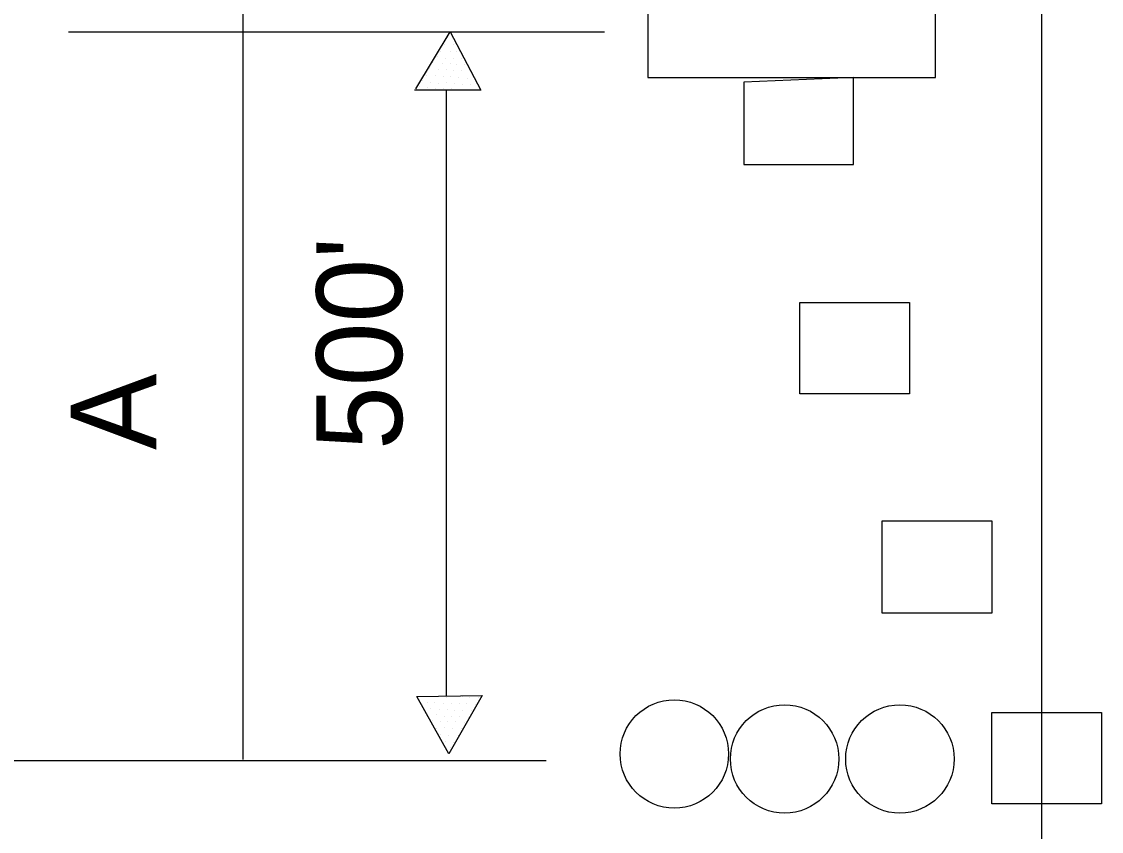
# Model space of a CAD drawing. Extents: x 610.92 to 617.75, y 610.91 to 620.34.
# Drawn here: x 615.094 to 615.85, y 618.032 to 618.599 of the extents above; entities that cross this region are included whole.
import ezdxf

# ---------------------------------------------------------------- set-up
doc = ezdxf.new("R2010")
doc.units = 0
for name, color, linetype in [('DETL-DIMS', 7, 'Continuous'), ('DETL-LINE', 7, 'Continuous'), ('DETL-NOTE', 7, 'Continuous'), ('USER-BORD', 7, 'Continuous')]:
    doc.layers.add(name, color=color, linetype=linetype)

# ---------------------------------------------------------------- blocks, each defined once
blk = doc.blocks.new('SIGN15')
at = {"layer": 'USER-BORD'}
for points in [[(-0.0013, 0.0018), (0.0011, 0.0019), (0.0011, 0.0037), (-0.0013, 0.0037)], [(-0.0031, 0.0018), (-0.0031, 0), (0.0032, 0), (0.0032, 0.0018)]]:
    blk.add_lwpolyline(points, close=True, dxfattribs=at)

msp = doc.modelspace()

# ---------------------------------------------------------------- linework, layer by layer
at = {"layer": 'DETL-DIMS'}
for p, q in [((615.24936, 618.082), (615.24936, 619.7948)), ((615.12696, 618.5916), (615.50216, 618.5916)), ((615.37016, 618.5516), (615.39416, 618.5916)), ((615.37016, 618.5516), (615.39416, 618.5916)), ((615.39416, 618.5916), (615.41576, 618.5508)), ((615.39416, 618.5916), (615.41576, 618.5508)), ((615.39016, 618.5828), (615.39016, 618.5828)), ((615.39016, 618.5828), (615.39016, 618.5828)), ((615.39256, 618.5876), (615.39256, 618.5876)), ((615.39256, 618.5876), (615.39256, 618.5876)), ((615.39656, 618.5828), (615.39656, 618.5828)), ((615.39656, 618.5828), (615.39656, 618.5828)), ((615.38776, 618.578), (615.38776, 618.578)), ((615.38776, 618.578), (615.38776, 618.578)), ((615.39416, 618.578), (615.39416, 618.578)), ((615.39416, 618.578), (615.39416, 618.578)), ((615.39896, 618.578), (615.39896, 618.578)), ((615.39896, 618.578), (615.39896, 618.578)), ((615.38216, 618.57), (615.38216, 618.57)), ((615.38216, 618.57), (615.38216, 618.57)), ((615.38536, 618.574), (615.38536, 618.574)), ((615.38536, 618.574), (615.38536, 618.574)), ((615.38856, 618.5692), (615.38856, 618.5692)), ((615.38856, 618.5692), (615.38856, 618.5692)), ((615.39096, 618.5732), (615.39096, 618.5732)), ((615.39096, 618.5732), (615.39096, 618.5732)), ((615.39416, 618.5692), (615.39416, 618.5692)), ((615.39416, 618.5692), (615.39416, 618.5692)), ((615.39656, 618.5732), (615.39656, 618.5732)), ((615.39656, 618.5732), (615.39656, 618.5732)), ((615.39896, 618.5684), (615.39896, 618.5684)), ((615.39896, 618.5684), (615.39896, 618.5684)), ((615.40216, 618.5732), (615.40216, 618.5732)), ((615.40216, 618.5732), (615.40216, 618.5732)), ((615.40456, 618.5684), (615.40456, 618.5684)), ((615.40456, 618.5684), (615.40456, 618.5684)), ((615.37736, 618.5612), (615.37736, 618.5612)), ((615.37736, 618.5612), (615.37736, 618.5612)), ((615.37976, 618.566), (615.37976, 618.566)), ((615.37976, 618.566), (615.37976, 618.566)), ((615.38376, 618.5612), (615.38376, 618.5612)), ((615.38376, 618.5612), (615.38376, 618.5612)), ((615.38616, 618.5652), (615.38616, 618.5652)), ((615.38616, 618.5652), (615.38616, 618.5652)), ((615.38936, 618.5604), (615.38936, 618.5604)), ((615.38936, 618.5604), (615.38936, 618.5604)), ((615.39176, 618.5652), (615.39176, 618.5652)), ((615.39176, 618.5652), (615.39176, 618.5652)), ((615.39416, 618.5604), (615.39416, 618.5604)), ((615.39416, 618.5604), (615.39416, 618.5604)), ((615.39656, 618.5644), (615.39656, 618.5644)), ((615.39656, 618.5644), (615.39656, 618.5644)), ((615.39976, 618.5596), (615.39976, 618.5596)), ((615.39976, 618.5596), (615.39976, 618.5596)), ((615.40216, 618.5644), (615.40216, 618.5644)), ((615.40216, 618.5644), (615.40216, 618.5644)), ((615.40856, 618.5636), (615.40856, 618.5636)), ((615.40856, 618.5636), (615.40856, 618.5636)), ((615.37256, 618.5532), (615.37256, 618.5532)), ((615.37256, 618.5532), (615.37256, 618.5532)), ((615.37496, 618.5572), (615.37496, 618.5572)), ((615.37496, 618.5572), (615.37496, 618.5572)), ((615.37816, 618.5524), (615.37816, 618.5524)), ((615.37816, 618.5524), (615.37816, 618.5524)), ((615.38056, 618.5564), (615.38056, 618.5564)), ((615.38056, 618.5564), (615.38056, 618.5564)), ((615.38616, 618.5556), (615.38616, 618.5556)), ((615.38616, 618.5556), (615.38616, 618.5556)), ((615.39176, 618.5564), (615.39176, 618.5564)), ((615.39176, 618.5564), (615.39176, 618.5564)), ((615.39736, 618.5556), (615.39736, 618.5556)), ((615.39736, 618.5556), (615.39736, 618.5556)), ((615.40296, 618.5548), (615.40296, 618.5548)), ((615.40296, 618.5548), (615.40296, 618.5548)), ((615.40616, 618.5588), (615.40616, 618.5588)), ((615.40616, 618.5588), (615.40616, 618.5588)), ((615.40856, 618.5548), (615.40856, 618.5548)), ((615.40856, 618.5548), (615.40856, 618.5548)), ((615.36936, 618.5508), (615.36936, 618.5508)), ((615.41576, 618.5508), (615.36936, 618.5508)), ((615.41576, 618.5508), (615.36936, 618.5508)), ((615.36936, 618.5508), (615.36936, 618.5508)), ((615.38376, 618.5516), (615.38376, 618.5516)), ((615.38376, 618.5516), (615.38376, 618.5516)), ((615.38936, 618.5516), (615.38936, 618.5516)), ((615.38936, 618.5516), (615.38936, 618.5516)), ((615.39176, 618.1268), (615.39176, 618.5508)), ((615.39176, 618.1268), (615.39176, 618.5508)), ((615.39496, 618.5516), (615.39496, 618.5516)), ((615.39496, 618.5516), (615.39496, 618.5516)), ((615.40056, 618.5508), (615.40056, 618.5508)), ((615.40056, 618.5508), (615.40056, 618.5508)), ((615.37096, 618.126), (615.41656, 618.1268)), ((615.37096, 618.126), (615.41656, 618.1268)), ((615.39336, 618.086), (615.37096, 618.126)), ((615.39336, 618.086), (615.37096, 618.126)), ((615.37816, 618.122), (615.37816, 618.122)), ((615.37816, 618.122), (615.37816, 618.122)), ((615.38296, 618.122), (615.38296, 618.122)), ((615.38296, 618.122), (615.38296, 618.122)), ((615.38536, 618.126), (615.38536, 618.126)), ((615.38536, 618.126), (615.38536, 618.126)), ((615.38936, 618.1212), (615.38936, 618.1212)), ((615.38936, 618.1212), (615.38936, 618.1212)), ((615.39176, 618.1252), (615.39176, 618.1252)), ((615.39176, 618.1252), (615.39176, 618.1252)), ((615.41656, 618.1268), (615.39336, 618.086)), ((615.41656, 618.1268), (615.39336, 618.086)), ((615.39496, 618.1212), (615.39496, 618.1212)), ((615.39496, 618.1212), (615.39496, 618.1212)), ((615.39736, 618.126), (615.39736, 618.126)), ((615.39736, 618.126), (615.39736, 618.126)), ((615.40056, 618.1212), (615.40056, 618.1212)), ((615.40056, 618.1212), (615.40056, 618.1212)), ((615.40296, 618.126), (615.40296, 618.126)), ((615.40296, 618.126), (615.40296, 618.126)), ((615.40536, 618.1212), (615.40536, 618.1212)), ((615.40536, 618.1212), (615.40536, 618.1212)), ((615.40776, 618.1252), (615.40776, 618.1252)), ((615.40776, 618.1252), (615.40776, 618.1252)), ((615.41416, 618.1252), (615.41416, 618.1252)), ((615.41416, 618.1252), (615.41416, 618.1252)), ((615.41656, 618.1268), (615.41656, 618.1268)), ((615.41656, 618.1268), (615.41656, 618.1268)), ((615.37816, 618.114), (615.37816, 618.114)), ((615.37816, 618.114), (615.37816, 618.114)), ((615.38056, 618.118), (615.38056, 618.118)), ((615.38056, 618.118), (615.38056, 618.118)), ((615.38456, 618.1132), (615.38456, 618.1132)), ((615.38456, 618.1132), (615.38456, 618.1132)), ((615.38696, 618.1172), (615.38696, 618.1172)), ((615.38696, 618.1172), (615.38696, 618.1172)), ((615.39256, 618.1172), (615.39256, 618.1172)), ((615.39256, 618.1172), (615.39256, 618.1172)), ((615.39736, 618.1164), (615.39736, 618.1164)), ((615.39736, 618.1164), (615.39736, 618.1164)), ((615.40296, 618.1164), (615.40296, 618.1164)), ((615.40296, 618.1164), (615.40296, 618.1164)), ((615.40936, 618.1164), (615.40936, 618.1164)), ((615.40936, 618.1164), (615.40936, 618.1164)), ((615.41176, 618.1204), (615.41176, 618.1204)), ((615.41176, 618.1204), (615.41176, 618.1204)), ((615.38216, 618.1092), (615.38216, 618.1092)), ((615.38216, 618.1092), (615.38216, 618.1092)), ((615.38776, 618.1084), (615.38776, 618.1084)), ((615.38776, 618.1084), (615.38776, 618.1084)), ((615.39016, 618.1124), (615.39016, 618.1124)), ((615.39016, 618.1124), (615.39016, 618.1124)), ((615.39256, 618.1084), (615.39256, 618.1084)), ((615.39256, 618.1084), (615.39256, 618.1084)), ((615.39496, 618.1124), (615.39496, 618.1124)), ((615.39496, 618.1124), (615.39496, 618.1124)), ((615.39816, 618.1084), (615.39816, 618.1084)), ((615.39816, 618.1084), (615.39816, 618.1084)), ((615.40056, 618.1124), (615.40056, 618.1124)), ((615.40056, 618.1124), (615.40056, 618.1124)), ((615.40456, 618.1076), (615.40456, 618.1076)), ((615.40456, 618.1076), (615.40456, 618.1076)), ((615.40696, 618.1116), (615.40696, 618.1116)), ((615.40696, 618.1116), (615.40696, 618.1116)), ((615.38456, 618.1036), (615.38456, 618.1036)), ((615.38456, 618.1036), (615.38456, 618.1036)), ((615.38776, 618.0996), (615.38776, 618.0996)), ((615.38776, 618.0996), (615.38776, 618.0996)), ((615.39016, 618.1044), (615.39016, 618.1044)), ((615.39016, 618.1044), (615.39016, 618.1044)), ((615.39336, 618.0988), (615.39336, 618.0988)), ((615.39336, 618.0988), (615.39336, 618.0988)), ((615.39576, 618.1036), (615.39576, 618.1036)), ((615.39576, 618.1036), (615.39576, 618.1036)), ((615.39976, 618.0988), (615.39976, 618.0988)), ((615.39976, 618.0988), (615.39976, 618.0988)), ((615.40216, 618.1036), (615.40216, 618.1036)), ((615.40216, 618.1036), (615.40216, 618.1036)), ((615.39096, 618.0948), (615.39096, 618.0948)), ((615.39096, 618.0948), (615.39096, 618.0948)), ((615.39656, 618.094), (615.39656, 618.094)), ((615.39656, 618.094), (615.39656, 618.094)), ((615.39416, 618.09), (615.39416, 618.09)), ((615.39416, 618.09), (615.39416, 618.09)), ((614.33816, 618.0812), (615.46136, 618.0812))]:
    msp.add_line(p, q, dxfattribs=at)
at = {"layer": 'DETL-LINE'}
msp.add_line((615.80856, 613.3204), (615.80856, 620.3372), dxfattribs=at)
for points in [[(615.63896, 618.338), (615.63896, 618.402), (615.71576, 618.402), (615.71576, 618.338)], [(615.63896, 618.338), (615.63896, 618.402), (615.71576, 618.402), (615.71576, 618.338)], [(615.63896, 618.338), (615.63896, 618.402), (615.71576, 618.402), (615.71576, 618.338)], [(615.69656, 618.1844), (615.69656, 618.2492), (615.77336, 618.2492), (615.77336, 618.1844)], [(615.77336, 618.0508), (615.77336, 618.1148), (615.85016, 618.1148), (615.85016, 618.0508)], [(615.77336, 618.0508), (615.77336, 618.1148), (615.85016, 618.1148), (615.85016, 618.0508)], [(615.77336, 618.0508), (615.77336, 618.1148), (615.85016, 618.1148), (615.85016, 618.0508)]]:
    msp.add_lwpolyline(points, close=True, dxfattribs=at)
for centre in [(615.55116, 618.08582), (615.62837, 618.08231), (615.70908, 618.08231)]:
    msp.add_circle(centre, 0.03796, dxfattribs=at)

# ---------------------------------------------------------------- block references
at = {"layer": 'DETL-LINE', "xscale": 32, "yscale": 32, "rotation": 180}
msp.add_blockref('SIGN15', (615.63492, 618.61716), dxfattribs=at)

# ---------------------------------------------------------------- texts
at = {"layer": 'DETL-NOTE'}
for s, p in [("500'", (615.36052, 618.29876)), ('A', (615.18852, 618.29876))]:
    msp.add_text(s, height=0.06, rotation=90, dxfattribs=at).set_placement(p)

doc.saveas('drawing.dxf')
